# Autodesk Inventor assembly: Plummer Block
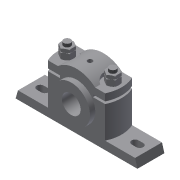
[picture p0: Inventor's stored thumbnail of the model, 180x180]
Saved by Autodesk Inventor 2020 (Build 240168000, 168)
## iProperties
Created: 2011-07
Part Number: Plummer Block
Document SubType Name: Assembly
Designer: CadCim
Author: CadCim
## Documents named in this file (7)
- D:\Autodesk Inventor_2020\Resources\Resources\Inventor_2020_tut\Inventor_2020_tut\c09_Inv_2020_tut\c09_Inv_tut_2020\c09_tut02_inv\Plummer Block\Plummer Block.iam
- D:\Autodesk Inventor_2020\Resources\Resources\Inventor_2020_tut\Inventor_2020_tut\c09_Inv_2020_tut\c09_Inv_tut_2020\c09_tut02_inv\Plummer Block\Casting.ipt
- D:\Autodesk Inventor_2020\Resources\Resources\Inventor_2020_tut\Inventor_2020_tut\c09_Inv_2020_tut\c09_Inv_tut_2020\c09_tut02_inv\Plummer Block\Brasses.ipt
- D:\Autodesk Inventor_2020\Resources\Resources\Inventor_2020_tut\Inventor_2020_tut\c09_Inv_2020_tut\c09_Inv_tut_2020\c09_tut02_inv\Plummer Block\Cap.ipt
- D:\Autodesk Inventor_2020\Resources\Resources\Inventor_2020_tut\Inventor_2020_tut\c09_Inv_2020_tut\c09_Inv_tut_2020\c09_tut02_inv\Plummer Block\Bolt.ipt
- D:\Autodesk Inventor_2020\Resources\Resources\Inventor_2020_tut\Inventor_2020_tut\c09_Inv_2020_tut\c09_Inv_tut_2020\c09_tut02_inv\Plummer Block\Nut.ipt
- D:\Autodesk Inventor_2020\Resources\Resources\Inventor_2020_tut\Inventor_2020_tut\c09_Inv_2020_tut\c09_Inv_tut_2020\c09_tut02_inv\Plummer Block\locknut.ipt
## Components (9 placed, 6 different names)
1. Casting:1 — Mate:1, Mate:2, Insert:1, Angle:1, Insert:2, Angle:2
2. Brasses:1 — Mate:1, Mate:2, Mate:3, Mate:4
3. Cap:1 — Mate:3, Mate:4, Insert:3, Insert:4
4. Bolt:1 — Insert:1, Angle:1
5. Bolt:2 — Insert:2, Angle:2
6. Nut:4 — Insert:3, Insert:5, Angle:4
7. Nut:5 — Insert:4, Insert:6, Angle:3
8. locknut:1 — Insert:5, Angle:4
9. locknut:2 — Insert:6, Angle:3
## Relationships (14: Insert 6, Mate 4, Angle 4)
- Mate:1: Casting:1 ↔ Brasses:1
- Mate:2: Casting:1 ↔ Brasses:1
- Mate:3: Brasses:1 ↔ Cap:1
- Mate:4: Brasses:1 ↔ Cap:1
- Insert:1: Casting:1 ↔ Bolt:1
- Angle:1: Casting:1 ↔ Bolt:1
- Insert:2: Casting:1 ↔ Bolt:2
- Angle:2: Casting:1 ↔ Bolt:2
- Insert:3: Cap:1 ↔ Nut:4
- Insert:4: Cap:1 ↔ Nut:5
- Insert:5: Nut:4 ↔ locknut:1
- Insert:6: Nut:5 ↔ locknut:2
- Angle:3: Nut:5 ↔ locknut:2
- Angle:4: Nut:4 ↔ locknut:1
